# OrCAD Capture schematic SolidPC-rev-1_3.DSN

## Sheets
1 uSOM: size D; title: SolidPC; rev: 1.3
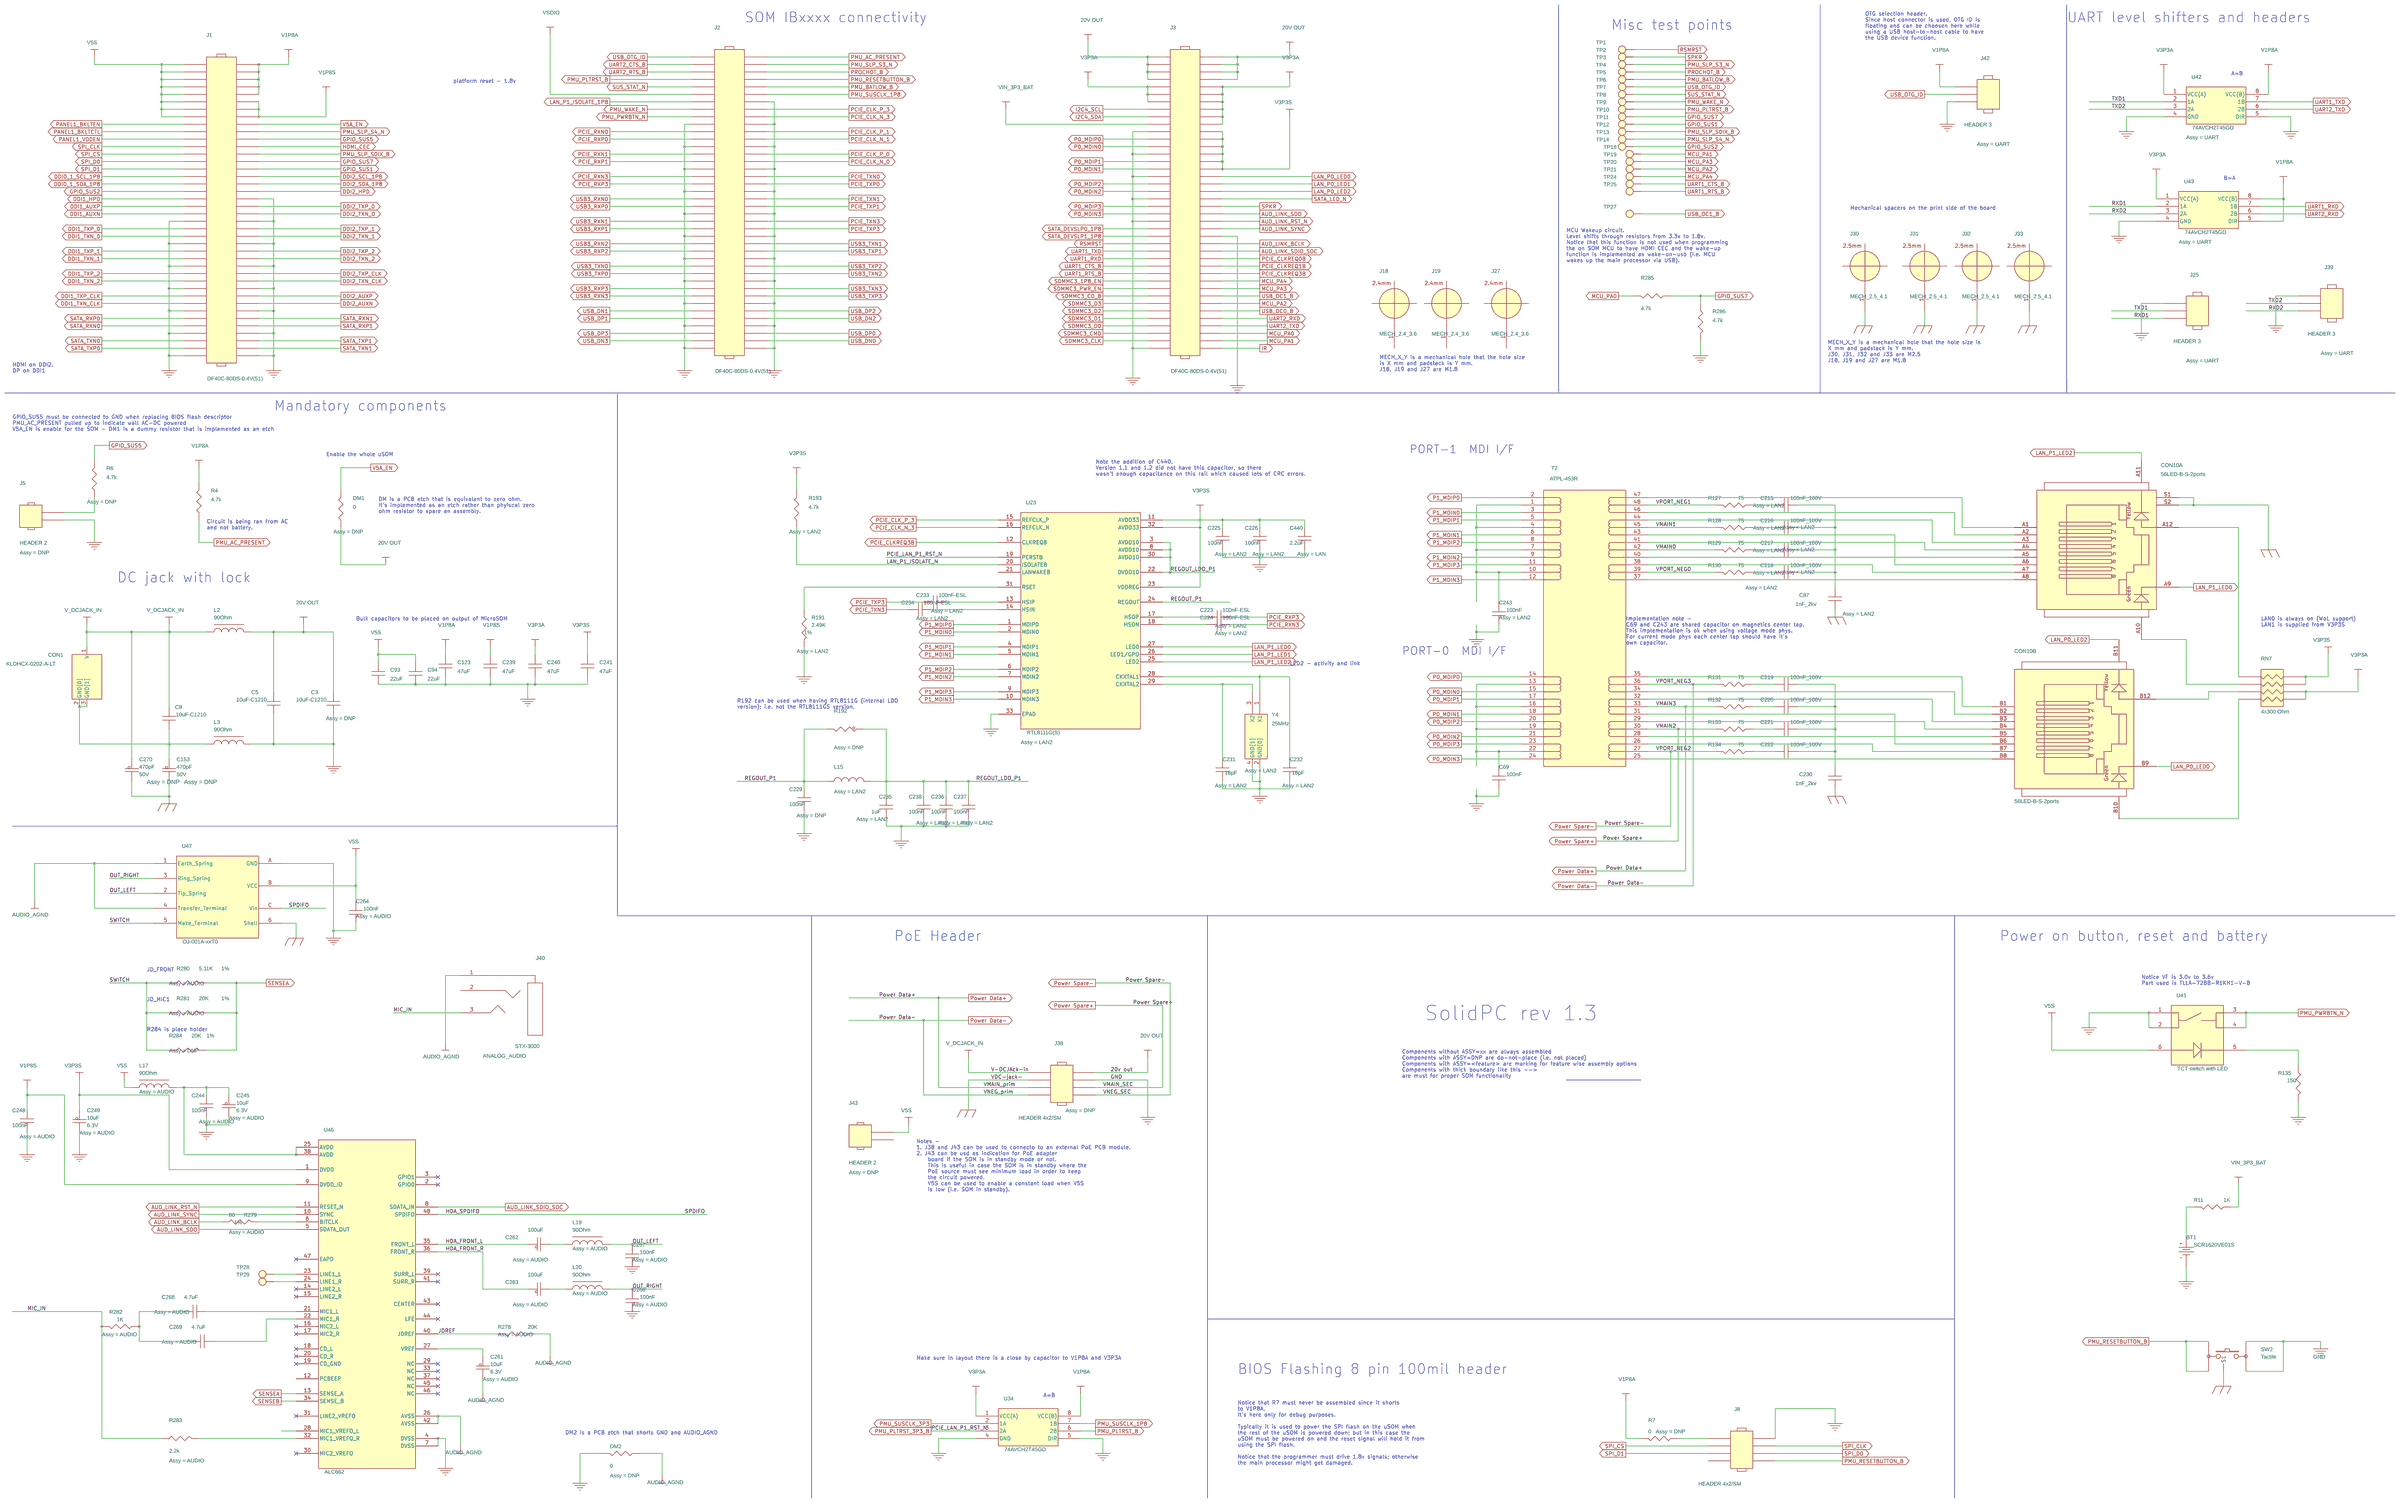
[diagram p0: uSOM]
2 External connectors: size D; rev: 1.1
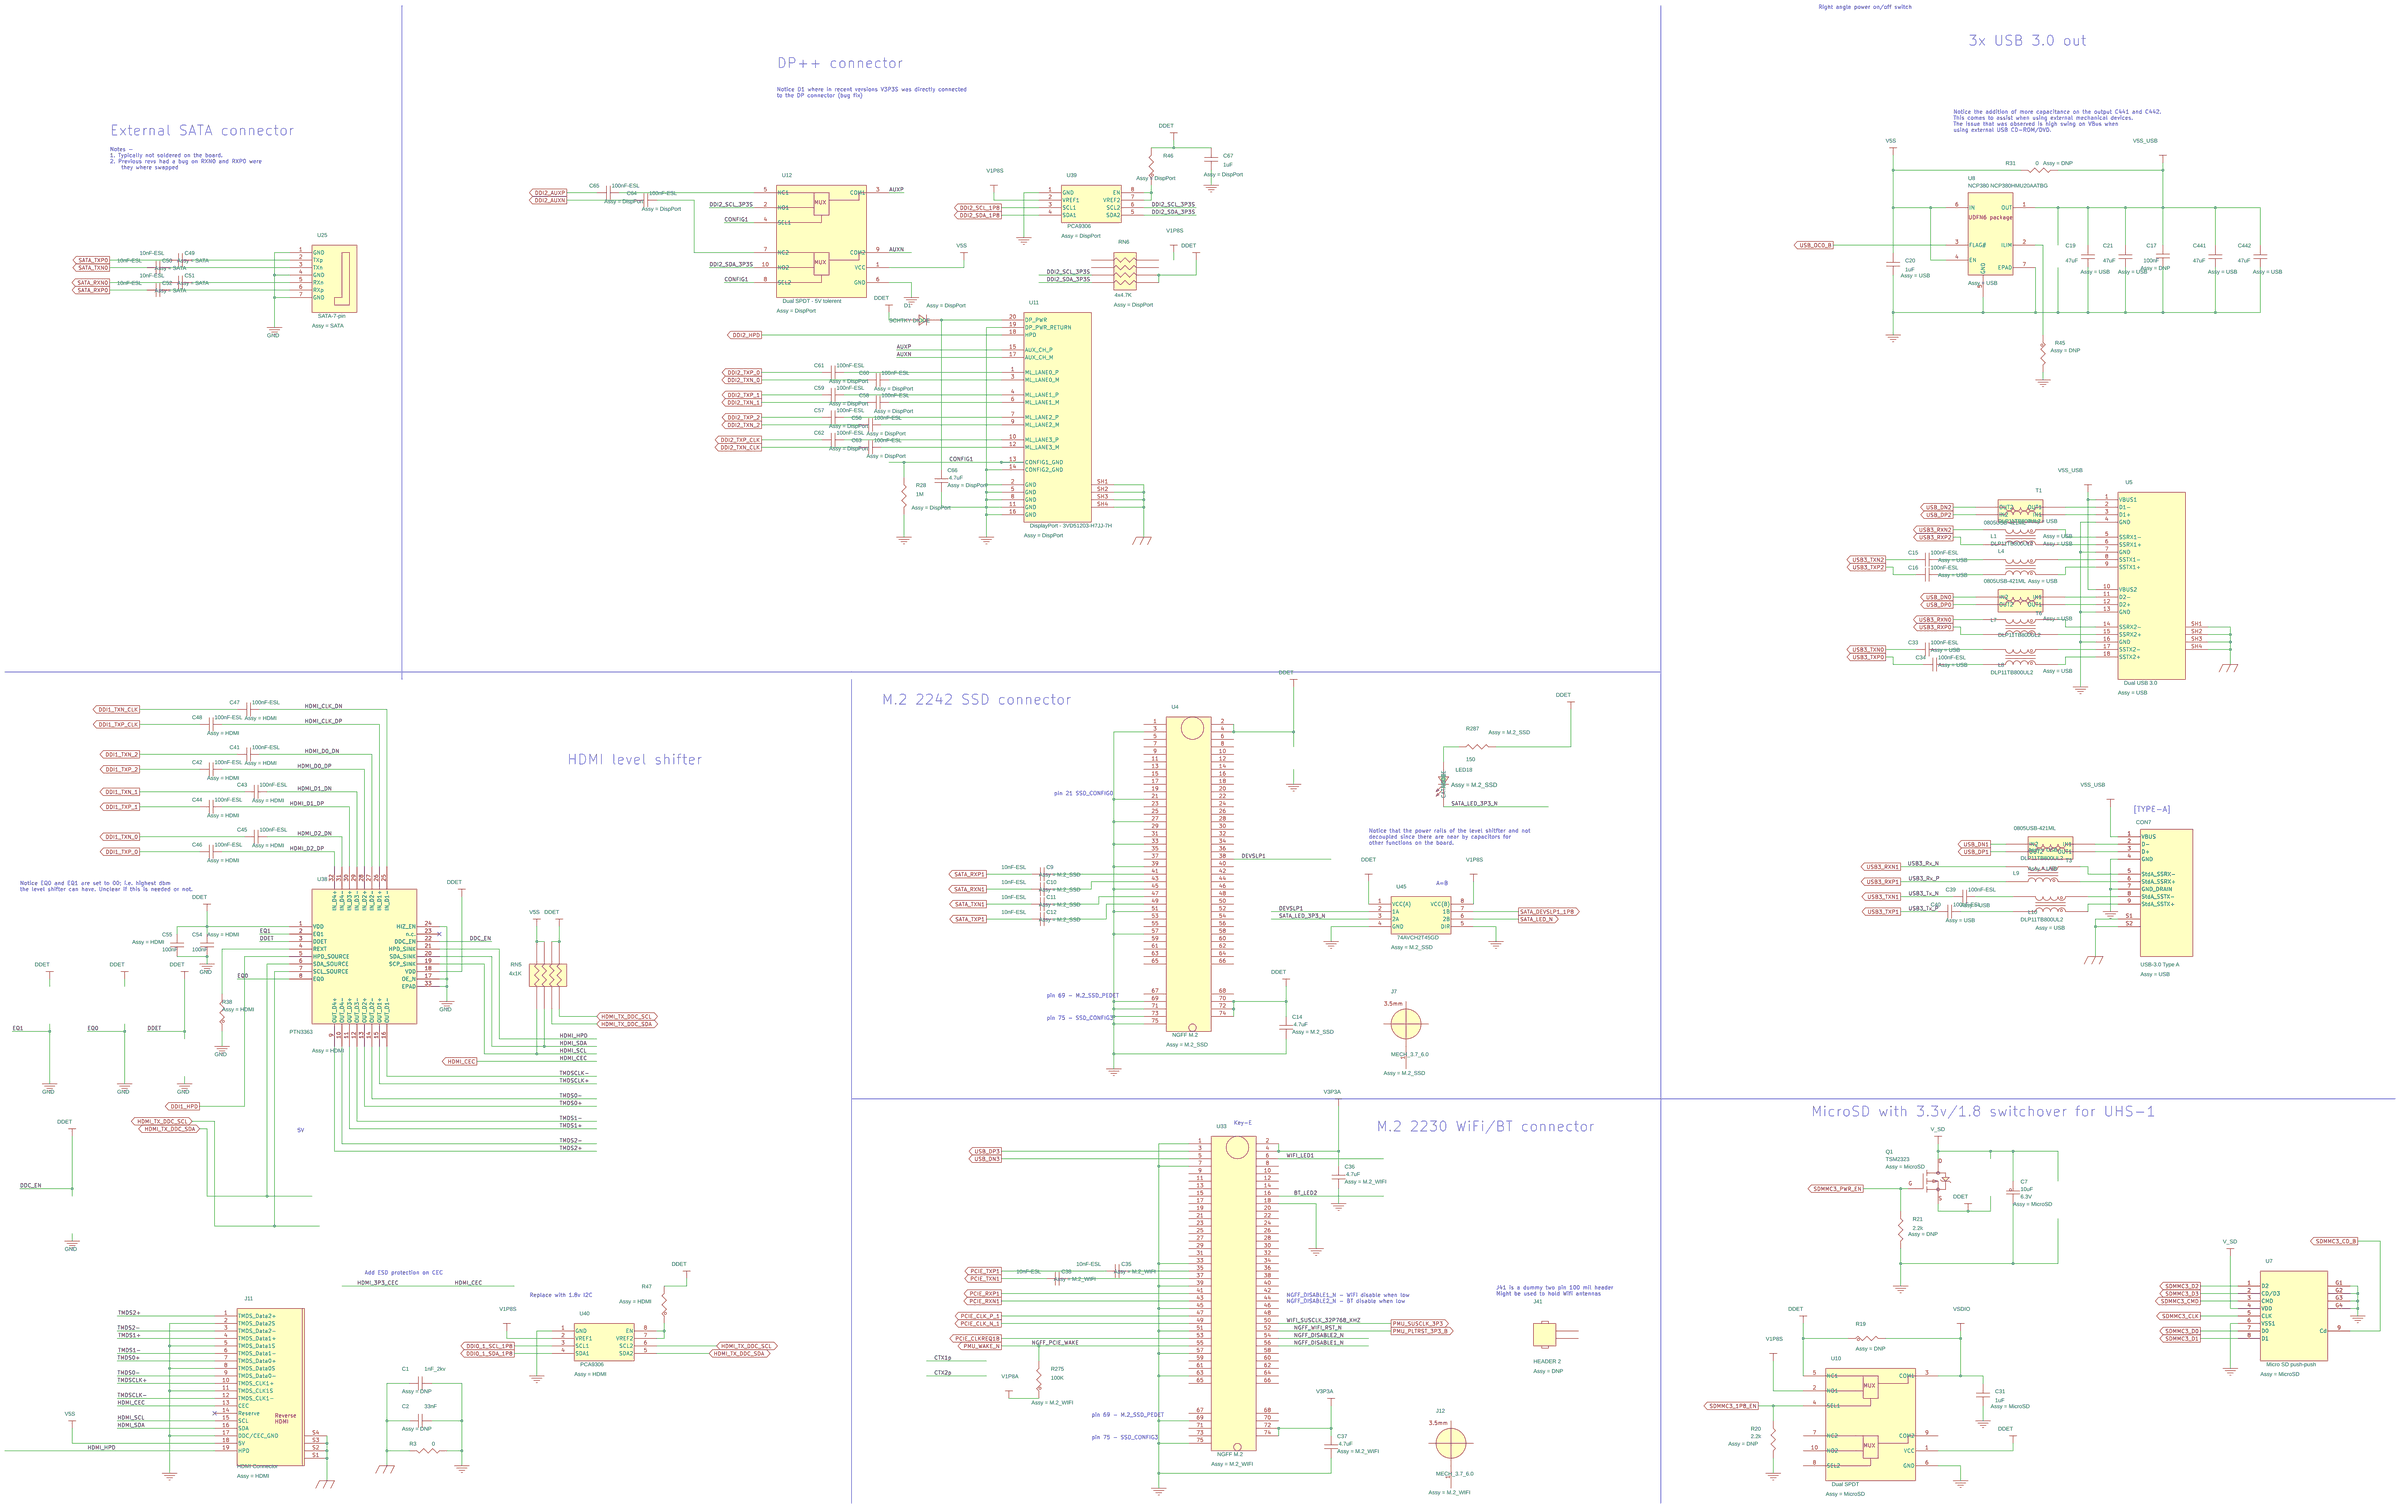
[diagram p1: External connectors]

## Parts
sheet External connectors
C1  1nF_2kv  [C1210]
C2  33nF  [C0402]
C7  10uF  [0603]
C9  10nF-ESL  [C0402]
C10  10nF-ESL  [C0402]
C11  10nF-ESL  [C0402]
C12  10nF-ESL  [C0402]
C14  4.7uF  [C0603]
C15  100nF-ESL  [C0402]
C16  100nF-ESL  [C0402]
C17  100nF  [C0402]
C19  47uF  [C1206]
C20  1uF  [C0402]
C21  47uF  [C1206]
C31  1uF  [0402]
C33  100nF-ESL  [C0402]
C34  100nF-ESL  [C0402]
C35  10nF-ESL  [C0402]
C36  4.7uF  [C0603]
C37  4.7uF  [C0603]
C38  10nF-ESL  [C0402]
C39  100nF-ESL  [C0402]
C40  100nF-ESL  [C0402]
C41  100nF-ESL  [C0402]
C42  100nF-ESL  [C0402]
C43  100nF-ESL  [C0402]
C44  100nF-ESL  [C0402]
C45  100nF-ESL  [C0402]
C46  100nF-ESL  [C0402]
C47  100nF-ESL  [C0402]
C48  100nF-ESL  [C0402]
C49  10nF-ESL  [C0402]
C50  10nF-ESL  [C0402]
C51  10nF-ESL  [C0402]
C52  10nF-ESL  [C0402]
C54  100nF  [C0402]
C55  100nF  [C0402]
C56  100nF-ESL  [C0402]
C57  100nF-ESL  [C0402]
C58  100nF-ESL  [C0402]
C59  100nF-ESL  [C0402]
C60  100nF-ESL  [C0402]
C61  100nF-ESL  [C0402]
C62  100nF-ESL  [C0402]
C63  100nF-ESL  [C0402]
C64  100nF-ESL  [C0402]
C65  100nF-ESL  [C0402]
C66  4.7uF  [C0603]
C67  1uF  [0402]
C441  47uF  [C1206]
C442  47uF  [C1206]
CON7  USB-3.0 Type A  [U3F09D-F1N2]
D1  SCHTKY DIODE  [DO-214AC]
J7  MECH_3.7_6.0  [MECH_3.7_6.0]
J11  HDMI Connector  [ABA-HDM-051]
J12  MECH_3.7_6.0  [MECH_3.7_6.0]
J41  HEADER 2
L1  DLP11TB800UL2  [DLP11TB800UL2]
L4  DLP11TB800UL2  [DLP11TB800UL2]
L7  DLP11TB800UL2  [DLP11TB800UL2]
L8  DLP11TB800UL2  [DLP11TB800UL2]
L9  DLP11TB800UL2  [DLP11TB800UL2]
L10  DLP11TB800UL2  [DLP11TB800UL2]
LED18  LED  [N/A]
Q1  TSM2323  [SOT23]
R3  0  [R0402]
R19  0  [0402]
R20  2.2k  [0402]
R21  2.2k  [0402]
R28  1M  [R0402]
R31  0  [R0402]
R38  12.4K  [0402]
R45  0  [0402]
R46  200K  [0402]
R47  200K  [0402]
R275  100K  [R0402]
R287  150  [R0402]
RN5  4x1K  [4xR0402]
RN6  4x4.7K  [YC124]
T1  0805USB-421ML  [CHOKE_0805]
T3  0805USB-421ML  [CHOKE_0805]
T6  0805USB-421ML  [CHOKE_0805]
U4  NGFF M.2  [NGFF]
U5  Dual USB 3.0
U7  Micro SD push-push  [ZM90]
U8  NCP380 NCP380HMU20AATBG  [TSOP-5]
U10  Dual SPDT  [R-PUQFN-N10]
U11  DisplayPort - 3VD51203-H7JJ-7H
U12  Dual SPDT - 5V tolerent  [R-PUQFN-N10]
U25  SATA-7-pin  [SATA-7-PIN]
U33  NGFF M.2  [NGFF]
U38  PTN3363  [HVQFN32]
U39  PCA9306  [US8]
U40  PCA9306  [US8]
U45  74AVCH2T45GD  [XSON8-SOT1116]
sheet uSOM
BT1  SCR1620VE01S  [N/A]
C3  10uF-C1210  [C1210]
C5  10uF-C1210  [C1210]
C8  10uF-C1210  [C1210]
C69  100nF  [C0402]
C87  1nF_2kv  [C1210]
C93  22uF  [C0603]
C94  22uF  [C0603]
C123  47uF  [C0805]
C153  470pF  [0402]
C215  100nF_100V  [C0603]
C216  100nF_100V  [C0603]
C217  100nF_100V  [C0603]
C218  100nF_100V  [C0603]
C219  100nF_100V  [C0603]
C220  100nF_100V  [C0603]
C221  100nF_100V  [C0603]
C222  100nF_100V  [C0603]
C223  100nF-ESL  [C0402]
C224  100nF-ESL  [C0402]
C225  100nF  [C0402]
C226  100nF  [C0402]
C229  100nF  [C0402]
C230  1nF_2kv  [C1210]
C231  18pF  [C0402]
C232  18pF  [C0402]
C233  100nF-ESL  [C0402]
C234  100nF-ESL  [C0402]
C235  1uF  [C0402]
C236  100nF  [C0402]
C237  100nF  [C0402]
C238  100nF  [C0402]
C239  47uF  [C0805]
C240  47uF  [C0805]
C241  47uF  [C0805]
C243  100nF  [C0402]
C244  100nF  [C0402]
C245  10uF  [0603]
C248  100nF  [C0402]
C249  10uF  [0603]
C261  10uF  [0603]
C262  100uF  [1210]
C263  100uF  [1210]
C264  100nF  [C0402]
C266  100nF  [C0402]
C267  100nF  [C0402]
C268  4.7uF  [C0603]
C269  4.7uF  [C0603]
C270  470pF  [0402]
C440  2.2uF  [C0402]
CON1  KLDHCX-0202-A-LT
CON10  56LED-B-S-2ports  [56LED-B-S-6ports]  (sections A,B)
DM1  0  [R0402]
DM2  0  [R0402]
J1  DF40C-80DS-0.4V(51)  [DF40HC-80DS]
J2  DF40C-80DS-0.4V(51)  [DF40HC-80DS]
J3  DF40C-80DS-0.4V(51)  [DF40HC-80DS]
J5  HEADER 2
J8  HEADER 4x2/SM  [M20]
J18  MECH_2.4_3.6  [MECH_2.4_3.6]
J19  MECH_2.4_3.6  [MECH_2.4_3.6]
J25  HEADER 3  [Header_3x1]
J27  MECH_2.4_3.6  [MECH_2.4_3.6]
J30  MECH_2.5_4.1  [MECH_2.5_4.1]
J31  MECH_2.5_4.1  [MECH_2.5_4.1]
J32  MECH_2.5_4.1  [MECH_2.5_4.1]
J33  MECH_2.5_4.1  [MECH_2.5_4.1]
J38  HEADER 4x2/SM  [M20]
J39  HEADER 3  [Header_3x1]
J40  STX-3000  [STX-3000]
J42  HEADER 3  [Header_3x1]
J43  HEADER 2
L2  90Ohm  [0805]
L3  90Ohm  [0805]
L15  4.7uH  [0806]
L17  90Ohm  [0805]
L19  90Ohm  [0805]
L20  90Ohm  [0805]
R4  4.7k  [R0402]
R6  4.7k  [R0402]
R7  0  [R0402]
R11  1K  [R0402]
R127  75  [R0402]
R128  75  [R0402]
R129  75  [R0402]
R130  75  [R0402]
R131  75  [R0402]
R132  75  [R0402]
R133  75  [R0402]
R134  75  [R0402]
R135  150  [R0402]
R191  2.49K  [R0402]
R192  0  [0402]
R193  4.7k  [R0402]
R278  20K  [R0402]
R279  80  [R0402]
R280  5.11K  [R0402]
R281  20K  [R0402]
R282  1K  [R0402]
R283  2.2k  [0402]
R284  20K  [R0402]
R285  4.7k  [R0402]
R286  4.7k  [R0402]
RN7  4x300 Ohm  [YC124]
SW2  Tactile  [N/A]
T2  ATPL-453R  [ATPL-453R]
TP1  TP_TH08  [HOLE_0p8]
TP2  TP_TH08  [HOLE_0p8]
TP3  TP_TH08  [HOLE_0p8]
TP4  TP_TH08  [HOLE_0p8]
TP5  TP_TH08  [HOLE_0p8]
TP6  TP_TH08  [HOLE_0p8]
TP7  TP_TH08  [HOLE_0p8]
TP8  TP_TH08  [HOLE_0p8]
TP9  TP_TH08  [HOLE_0p8]
TP10  TP_TH08  [HOLE_0p8]
TP11  TP_TH08  [HOLE_0p8]
TP12  TP_TH08  [HOLE_0p8]
TP13  TP_TH08  [HOLE_0p8]
TP14  TP_TH08  [HOLE_0p8]
TP18  TP_TH08  [HOLE_0p8]
TP19  TP_TH08  [HOLE_0p8]
TP20  TP_TH08  [HOLE_0p8]
TP21  TP_TH08  [HOLE_0p8]
TP24  TP_TH08  [HOLE_0p8]
TP25  TP_TH08  [HOLE_0p8]
TP27  TP_TH08  [HOLE_0p8]
TP28  TP_TH08  [HOLE_0p8]
TP29  TP_TH08  [HOLE_0p8]
U23  RTL8111G(S)  [QFN32]
U34  74AVCH2T45GD  [XSON8-SOT1116]
U41  TCT switch with LED
U42  74AVCH2T45GD  [XSON8-SOT1116]
U43  74AVCH2T45GD  [XSON8-SOT1116]
U46  ALC662  [LQFP-48]
U47  OJ-001A-xxT0
Y4  25MHz  [S3225]

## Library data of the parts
C1 = Cap: CHIP CAP 1nF 2KV 1610; Assy: DNP; MFG_NAME01: Hitano; MFG_PN01: 1210N102J202NT; Manufacturer: Hitano; Manufacturer Name: Hitano; Manufacturer P/N: 1210N102J202NT; PRIORITY_PN: CA60001; SolidRun P/N: CA60001; Updated: 2015-09-14 13:40:19; Datasheet: <null>
C2 = Cap: CHIP CAP 33nF 6.3V 0402 X5R; Assy: DNP; MFG_NAME01: SAMSUNG; MFG_PN01: CL05B333KP5NNNC; Manufacturer: Murata; Manufacturer Name: Murata; Manufacturer P/N: GRM155R71A333KA01D; SolidRun P/N: CA20011; Updated: 2015-09-14 13:40:19; Datasheet: <null>
C7 = CAP_NP: CAP CER 10UF 6.3V 10% X5R 0603; AGILE_PN: 150-77832; Assy: MicroSD; CAD_APPROVED: Yes; FPLIST: CC0603_OV,CC0603,0603_CC; HEIGHT: 1.0MM; MFG_NAME01: TDK; MFG_PN01: C1608X5R0J106KT; ROHS: Yes; SIGNAL_MODEL: DEFAULT_CAPACITOR_1e+07pF_2_1; SolidRun P/N: CA30001; Tolerance: 10%; VOLTAGE: 6.3V; WVDC: 6.3V
C9-C12 = Cap: CHIP CAP 10nF 25V 0402 X7R; Assy: M.2_SSD; Manufacturer: Capax; Manufacturer P/N: 0402X103K250SNT; Part Number: 0402X103K250SNT; Power: 0; SolidRun P/N: CA20002; Tolerance: 10%; Datasheet: <null>
C14 = Cap: CAP CER 0603 4.7UF 10V 10% X5R; Assy: M.2_SSD; Manufacturer: Hitano; Manufacturer P/N: 0603B475K160NU; Part Number: C4750805-X5R-25V; SolidRun P/N: CA30003; Updated: 2015-02-17 20:35:06; Datasheet: <null>
C15 C16 C33 C34 C39 C40 = Cap: CAP CER 100NF 16V 10% X7R 0402; Assy: USB; FPLIST: 0402_SQR21,0402_RND,0402; Manufacturer: CAPAX; Manufacturer P/N: 0402X104K250SNT; Part Number: 0402X104K250SNT; SolidRun P/N: CA20090; Updated: 2015-02-17 20:35:06; Datasheet: <null>
C17 = Cap: CAP CER 0402 100nF 10V 10% X7R; Assy: DNP; FPLIST: 0402_SQR21,0402_RND,0402; Manufacturer: samsung; Manufacturer P/N: CL05B104KP5NNNC; Part Number: C1040402-X7R-16V; SolidRun P/N: CA20001; Updated: 2015-02-17 20:35:06; Datasheet: <null>
C19 C21 C441 C442 = Cap: CAP CER 1206 47UF 6.3V 20% X5R; Assy: USB; Manufacturer: murata; Manufacturer P/N: GRM31CR60J476ME19L; Part Number: GMC31X5R476M10NTLF; SolidRun P/N: CA50001; Updated: 2015-02-17 20:35:06; Datasheet: <null>
C20 = Cap: CAP CER 0402 1uF 10V 10% X5R; Assy: USB; Manufacturer: samsung; Manufacturer P/N: CL05A105KP5NNNC; Part Number: C1050603-X7R-16V; SolidRun P/N: CA20005; Updated: 2015-02-17 20:35:06; Datasheet: <null>
C31 = Cap: CHIP CAP 33nF 6.3V 0402 X5R; Assy: MicroSD; MFG_NAME01: SAMSUNG; MFG_PN01: CL05B333KP5NNNC; SolidRun P/N: CA20005; Tolerance: 20%
C35 C38 = Cap: CHIP CAP 10nF 25V 0402 X7R; Assy: M.2_WIFI; Manufacturer: Capax; Manufacturer P/N: 0402X103K250SNT; Part Number: 0402X103K250SNT; Power: 0; SolidRun P/N: CA20002; Tolerance: 10%; Datasheet: <null>
C36 C37 = Cap: CAP CER 0603 4.7UF 10V 10% X5R; Assy: M.2_WIFI; Manufacturer: Hitano; Manufacturer P/N: 0603B475K160NU; Part Number: C4750805-X5R-25V; SolidRun P/N: CA30003; Updated: 2015-02-17 20:35:06; Datasheet: <null>
C41-C48 = Cap: CAP CER 100NF 16V 10% X7R 0402; Assy: HDMI; FPLIST: 0402_SQR21,0402_RND,0402; Manufacturer: CAPAX; Manufacturer P/N: 0402X104K250SNT; Part Number: 0402X104K250SNT; SolidRun P/N: CA20090; Updated: 2015-02-17 20:35:06; Datasheet: <null>
C49-C52 = Cap: CHIP CAP 10nF 25V 0402 X7R; Assy: SATA; Manufacturer: Capax; Manufacturer P/N: 0402X103K250SNT; Part Number: 0402X103K250SNT; Power: 0; SolidRun P/N: CA20002; Tolerance: 10%; Datasheet: <null>
C54 C55 = Cap: CAP CER 0402 100nF 10V 10% X7R; Assy: HDMI; Manufacturer: samsung; Manufacturer P/N: CL05B104KP5NNNC; Part Number: C1040402-X7R-16V; Power: <null>; SolidRun P/N: CA20001; Tolerance: 6.3V 20% X7R; Datasheet: <null>
C56-C65 = Cap: CAP CER 100NF 16V 10% X7R 0402; Assy: DispPort; FPLIST: 0402_SQR21,0402_RND,0402; Manufacturer: CAPAX; Manufacturer P/N: 0402X104K250SNT; Part Number: 0402X104K250SNT; SolidRun P/N: CA20090; Updated: 2015-02-17 20:35:06; Datasheet: <null>
C66 = Cap: CAP CER 0603 4.7UF 10V 10% X5R; Assy: DispPort; Manufacturer: Hitano; Manufacturer P/N: 0603B475K160NU; Part Number: C4750805-X5R-25V; SolidRun P/N: CA30003; Updated: 2015-02-17 20:35:06; Datasheet: <null>
C67 = Cap: CHIP CAP 33nF 6.3V 0402 X5R; Assy: DispPort; MFG_NAME01: SAMSUNG; MFG_PN01: CL05B333KP5NNNC; SolidRun P/N: CA20005; Tolerance: 20%
CON7 = USB3_2: USB-3.0 Host connector; Assy: USB; Manufacturer: Genesis; Manufacturer P/N: USAR-2F09-AB63T1H; Part Number: USAR-2F09-AB63T1H; SolidRun P/N: CO00526; Updated: 2015-02-17 20:35:06; Datasheet: <null>
D1 = DIODE: Diode Schottky 30V 2A Surface Mount SMA; Assy: DispPort; Manufacturer: Diodes; Manufacturer P/N: B230A-13-F; SolidRun P/N: DI00225; Tolerance: 30V/2A; Datasheet: https://www.diodes.com/assets/Datasheets/ds13004.pdf
J7 = MECH_4.5_4: Assy: M.2_SSD; PRIORITY_PN: MCH0008; SolidRun P/N: MCH0008
J11 = HDMI_connector_0: Assy: HDMI; MFG_NAME01: LOTES; MFG_PN01: ABA-HDM-051-P01; SolidRun P/N: CO00559; Datasheet: http://www.lotes.cc/upload/Customer_drawing/HDMI/ABA-HDM-051_(REV.C).pdf
J12 = MECH_4.5_4: Assy: M.2_WIFI; PRIORITY_PN: MCH0008; SolidRun P/N: MCH0008
J5 J41 J43 = HEADER_2: Assy: DNP; Manufacturer: FCI; Note: 100 mil two pins; Power: 0; Price: 0.054; SolidRun P/N: CO00049; Source: Mouser; Source P/N: 649-68000-101HLF; Datasheet: http://portal.fciconnect.com/Comergent/adirect/fci?cmd=catCustomerDrawing&productName=68000-101HLF
L1 L4 L7-L10 = CHOKE_CMx2: Common Mode Filters / Chokes 0504 80ohm EMI Suppression Fltr; Assy: USB; Manufacturer: Murata; Manufacturer P/N: DLP11TB800UL2L; SolidRun P/N: IN00033; Updated: 2015-02-17 20:35:06; Datasheet: http://www.mouser.com/ds/2/281/Murata%20DL_PL%20Series-202927.pdf
LED18 = LED: Indication LED 0603 - Green; Assy: M.2_SSD; Manufacturer: Everlight; PRIORITY_PN: DI00210; SolidRun P/N: DI00210; Updated: 2015-02-17 20:35:06; Datasheet: http://download.siliconexpert.com/pdfs/2007/08/07/semi_b/manual/ele/lamps/ds300089.pdf
Q1 = IRF4905_TO_2: 20V P-Channel MOSFET; Assy: MicroSD; SolidRun P/N: IC00666
R3 = Resistor_tolerance_0: RES 0402 1/16W 0? 5%; FPLIST: RC0402_25,RC0402_HD,RC0402_X2,0402_CC; MFG_NAME01: YAGEO; MFG_PN01: RC0402JR-070RL; Manufacturer: Yageo; Manufacturer Name: Yageo; Manufacturer P/N: RC0402JR-070RL; Manufacturer's Part Number: RC0402JR-070RL; SolidRun P/N: RE20009; Updated: 2015-09-14 13:40:19; Datasheet: <null>
R19 R192 = RES: RES MF ZERO OHM 1/10W -- 0402; AGILE_PN: 470-79965; Assy: DNP; CAD_APPROVED: Yes; FPLIST: RC0402_25,RC0402_HD,RC0402_X2,0402_CC; ROHS: Yes; SIGNAL_MODEL: DEFAULT_RESISTOR_0.001OHM_2_1; SolidRun P/N: RE20009
R20 R21 = Resistor: CHIP RES 2.2K 1/16W 0402; Assy: DNP; MFG_NAME01: YAGEO; MFG_PN01: RC0402JR-072K2L; SolidRun P/N: RE20204; Tolerance: 5%
R28 = Resistor_tolerance_0: RES 0402 1/16W 1M 5%; Assy: DispPort; FPLIST: RC0402_25,RC0402_HD,RC0402_X2,0402_CC; MFG_NAME01: YAGEO; MFG_PN01: RC0402JR-070RL; Manufacturer: Yageo; Manufacturer P/N: RC0402FR-071ML; SolidRun P/N: RE20416; Updated: 2015-02-17 20:35:06
R7 R31 = Resistor: RES 0402 1/16W 0? 5%; Assy: DNP; Manufacturer: Yageo; Manufacturer P/N: RC0402JR-070RL; Part Number: R0000805; Power: <null>; SolidRun P/N: RE20009; Tolerance: NA; Datasheet: <null>
R38 = RES: RES MF 12.4 KOhm 0402 1%; AGILE_PN: 470-79965; Assy: HDMI; CAD_APPROVED: Yes; FPLIST: RC0402_25,RC0402_HD,RC0402_X2,0402_CC; ROHS: Yes; SIGNAL_MODEL: DEFAULT_RESISTOR_0.001OHM_2_1; SolidRun P/N: RE20457
R45 = RES: RES MF ZERO OHM 1/10W -- 0402; Assy: DNP; CAD_APPROVED: Yes; FPLIST: RC0402_25,RC0402_HD,RC0402_X2,0402_CC; ROHS: Yes; SIGNAL_MODEL: DEFAULT_RESISTOR_0.001OHM_2_1; SolidRun P/N: RE20009
R46 = RES: RES MF 200 KOHM 1/10W -- 0402; AGILE_PN: 470-79965; Assy: DispPort; CAD_APPROVED: Yes; FPLIST: RC0402_25,RC0402_HD,RC0402_X2,0402_CC; ROHS: Yes; SIGNAL_MODEL: DEFAULT_RESISTOR_0.001OHM_2_1; SolidRun P/N: RE20036
R47 = RES: RES MF 200 KOHM 1/10W -- 0402; AGILE_PN: 470-79965; Assy: HDMI; CAD_APPROVED: Yes; FPLIST: RC0402_25,RC0402_HD,RC0402_X2,0402_CC; ROHS: Yes; SIGNAL_MODEL: DEFAULT_RESISTOR_0.001OHM_2_1; SolidRun P/N: RE20036
R275 = RES: RES 0402 1/16W 100K 1%; Assy: M.2_WIFI; FPLIST: RC0402_25,RC0402_HD,0402_CC; ROHS: Yes; SIGNAL_MODEL: DEFAULT_RESISTOR_10000OHM_2_1; SolidRun P/N: RE20015; Tolerance: 1%; Updated: 2015-02-17 20:35:06; Datasheet: <null>
R287 = Resistor: RES 0402 1/16W 150 Ohm 1%; Assy: M.2_SSD; Manufacturer: Yageo; Manufacturer P/N: RC0402FR-0710KL; Part Number: R1030402-1%; Power: <null>; SolidRun P/N: RE20014; Tolerance: 5%; Datasheet: <null>
RN5 = RESISTOR_DIP_4: 4 Elements 1 KOhm 5%; Power: <null>; SolidRun P/N: RN00041; Tolerance: 1%; Datasheet: http://www.ctscorp.com/components/Datasheets/CTSChipArrayDs.pdf
RN6 = RESISTOR_DIP_4: 4.7K Resistor Network 4x0402 5%; Assy: DispPort; MFG_NAME01: YAGEO; MFG_PN01: YC124-JR-074K7L; Power: 0; SolidRun P/N: RN00002; Tolerance: 1%; Wattage: 1/10W; Datasheet: http://www.yageo.ru/pdf/YC124.pdf
T1 T3 T6 = DLW21HN121SQ2: Common Mode Filter USB 2.0; Assy: USB; Manufacturer: Coilcraft; Manufacturer P/N: 0805USB-421MLC; Part Number: 0805USB-421MLC; SolidRun P/N: IN00016; Updated: 2015-02-17 20:35:06; Datasheet: http://www.mouser.com/ds/2/597/0805usb-463502.pdf
U4 = NGFF_M.2: Assy: M.2_SSD; SolidRun P/N: CO00514
U5 = Dual_USB_3_0.0: Assy: USB; SolidRun P/N: CO00554
U7 = CJ-WK21923-R6SS6_0: SD/MMC card connector; Assy: MicroSD; MFG_NAME01: CEN LINK; MFG_PN01: ZM90-15000-0BR1; SolidRun P/N: CO00091; Datasheet: ZM90-15000-0BR1-(C).pdf
U8 = NCP380_2: Adjustable USB Current limiter; Assy: USB; Manufacturer: OnSemi; Manufacturer P/N: NCP380HMU20AATBG; SolidRun P/N: IC01034; Datasheet: http://www.onsemi.com/pub_link/Collateral/NCP380-D.PDF
U10 = Dual_SPDT: Dual analog switch; Assy: MicroSD; MFG_NAME01: TI; MFG_PN01: TS3A5223RSWR; SolidRun P/N: IC00220; Datasheet: http://www.mouser.com/ds/2/405/scds339a-261259.pdf
U11 = DisplayPort_-_3VD51203-H7JJ-7H: Display Port full size; Assy: DispPort; SolidRun P/N: CO00555
U12 = Dual_SPDT: Dual analog switch; Assy: DispPort; SolidRun P/N: IC01039
U25 = SATA-7-pin: Assy: SATA; SolidRun P/N: CO00513
U33 = NGFF_M.2: Assy: M.2_WIFI; SolidRun P/N: CO00552
U38 = PTN3363: DP to HDMI level shifter; Assy: HDMI; SolidRun P/N: IC01036
U39 = PCA9306: Assy: DispPort; SolidRun P/N: IC01040
U40 = PCA9306: Assy: HDMI; SolidRun P/N: IC01040
U45 = 74AVCH2T45GN: Dual-bit, dual-supply voltage level translator/transceiver; 3-state; Assy: M.2_SSD; SolidRun P/N: IC01021
BT1 = Battery_1: RTC Battery xV/yA; Manufacturer: JL Worldwide; Manufacturer P/N: <null>; Power: 0; Price: 0.26; SolidRun P/N: BT00001; Source: Mouser; Tolerance: <null>; Updated: 2015-09-14 13:40:19
C3 = Cap: CHIP CAP 10uF 50V 10% X7R 1210; Assy: DNP; Manufacturer: SAMSUNG; Manufacturer P/N: CL32B106KBJNNWE; SolidRun P/N: CA60004; Updated: 2015-07-16 09:53:12
C5 C8 = Cap: CHIP CAP 10uF 50V 10% X7R 1210; Manufacturer: SAMSUNG; Manufacturer P/N: CL32B106KBJNNWE; SolidRun P/N: CA60004; Updated: 2015-07-16 09:53:12
C69 = Cap: CAP CER 0402 100nF 10V 10% X7R; FPLIST: 0402_SQR21,0402_RND,0402; Manufacturer: samsung; Manufacturer P/N: CL05B104KP5NNNC; Part Number: C1040402-X7R-16V; SolidRun P/N: CA20001; Updated: 2015-02-17 20:35:06; Datasheet: <null>
C87 = Cap: CHIP CAP 1nF 2KV 1610; Assy: LAN2; MFG_NAME01: Hitano; MFG_PN01: 1210N102J202NT; Manufacturer: Hitano; Manufacturer P/N: 1210N102J202NT; PRIORITY_PN: CA60001; SolidRun P/N: CA60001; Updated: 2015-02-17 20:35:06; Datasheet: <null>
C93 C94 = Cap: CAP CER 0603 22UF 6.3V 20% X5R; Manufacturer: Samsung; Manufacturer P/N: CL10A226MQ8NRNE; Part Number: C2260805-X5R-6.3V; Power: <null>; SolidRun P/N: CA30002; Tolerance: 6.3V 20% X5R; Datasheet: <null>
C123 C239-C241 = Cap: CAP CER 0805 47UF 4V 20% X5R; Power: <null>; SolidRun P/N: CA40006; Tolerance: 4V 20% X5R; Datasheet: <null>
C153 C270 = CAP_NP: CAP CER 470PF 50V 10% X7R 0402; AGILE_PN: 150-75452; Assy: DNP; CAD_APPROVED: Yes; FPLIST: CC0402_25,CC0402_HD,0402_CC; HEIGHT: 0.55MM; MFG_NAME01: MURATA; MFG_PN01: GRM155R71H471KA01D; ROHS: Yes; ROOM: RGMII_PHY; SIGNAL_MODEL: DEFAULT_CAPACITOR_470pF_2_1; SolidRun P/N: CA20082; Tolerance: 10%; VOLTAGE: 50V; WVDC: 50V
C215-C218 = Cap: CAP CER 0.1 uF 100 V 10% X7R 0603; Assy: LAN2; FPLIST: 0402_SQR21,0402_RND,0402; Manufacturer: samsung; Manufacturer P/N: CL10B104KC8NNNC; Part Number: C1040402-X7R-16V; SolidRun P/N: CA30006; Updated: 2015-02-17 20:35:06; Datasheet: <null>
C219-C222 = Cap: CAP CER 0.1 uF 100 V 10% X7R 0603; FPLIST: 0402_SQR21,0402_RND,0402; Manufacturer: samsung; Manufacturer P/N: CL10B104KC8NNNC; Part Number: C1040402-X7R-16V; SolidRun P/N: CA30006; Updated: 2015-02-17 20:35:06; Datasheet: <null>
C223 C224 C233 C234 = Cap: CAP CER 100NF 16V 10% X7R 0402; Assy: LAN2; FPLIST: 0402_SQR21,0402_RND,0402; Manufacturer: CAPAX; Manufacturer P/N: 0402X104K250SNT; Part Number: 0402X104K250SNT; SolidRun P/N: CA20090; Updated: 2015-02-17 20:35:06; Datasheet: <null>
C225 C226 C236-C238 = Cap: CAP CER 0402 100nF 10V 10% X7R; Assy: LAN2; Manufacturer: samsung; Manufacturer P/N: CL05B104KP5NNNC; Part Number: C1040402-X7R-16V; Power: <null>; SolidRun P/N: CA20001; Tolerance: 6.3V 20% X7R; Datasheet: <null>
C229 = Cap: CAP CER 0402 100nF 10V 10% X7R; Assy: DNP; Manufacturer: samsung; Manufacturer P/N: CL05B104KP5NNNC; Part Number: C1040402-X7R-16V; Power: <null>; SolidRun P/N: CA20001; Tolerance: 6.3V 20% X7R; Datasheet: <null>
C230 = Cap: CHIP CAP 1nF 2KV 1610; MFG_NAME01: Hitano; MFG_PN01: 1210N102J202NT; Manufacturer: Hitano; Manufacturer P/N: 1210N102J202NT; PRIORITY_PN: CA60001; SolidRun P/N: CA60001; Updated: 2015-02-17 20:35:06; Datasheet: <null>
C231 C232 = Cap: CAP CER 0402 18pF 50V 5% C0G; Assy: LAN2; Manufacturer: Murata; Manufacturer P/N: GRM1555C1H220JA01D; Part Number: C2200402-NPO-50V; Power: <null>; SolidRun P/N: CA20017; Tolerance: 4V 5% C0G; Datasheet: <null>
C235 = Cap: CAP CER 0402 1uF 10V 10% X5R; Assy: LAN2; Manufacturer: samsung; Manufacturer P/N: CL05A105KP5NNNC; Part Number: C1050603-X7R-16V; Power: <null>; SolidRun P/N: CA20005; Tolerance: 6.3V 20% X5R; Datasheet: <null>
C243 = Cap: CAP CER 0402 100nF 10V 10% X7R; Assy: LAN2; FPLIST: 0402_SQR21,0402_RND,0402; Manufacturer: samsung; Manufacturer P/N: CL05B104KP5NNNC; Part Number: C1040402-X7R-16V; SolidRun P/N: CA20001; Updated: 2015-02-17 20:35:06; Datasheet: <null>
C244 C248 = Cap: CAP CER 0402 100nF 10V 10% X7R; Assy: AUDIO; Manufacturer: samsung; Manufacturer P/N: CL05B104KP5NNNC; Part Number: C1040402-X7R-16V; Power: <null>; SolidRun P/N: CA20001; Tolerance: 6.3V 20% X7R; Datasheet: <null>
C245 C249 C261 = CAP_NP: CAP CER 10UF 6.3V 10% X5R 0603; AGILE_PN: 150-77832; Assy: AUDIO; CAD_APPROVED: Yes; FPLIST: CC0603_OV,CC0603,0603_CC; HEIGHT: 1.0MM; MFG_NAME01: TDK; MFG_PN01: C1608X5R0J106KT; ROHS: Yes; SIGNAL_MODEL: DEFAULT_CAPACITOR_1e+07pF_2_1; SolidRun P/N: CA30001; Tolerance: 10%; VOLTAGE: 6.3V; WVDC: 6.3V
C262 C263 = CAP_NP: CAP CER 100UF 6.3V 20% X5R 1210; AGILE_PN: 150-77832; Assy: AUDIO; CAD_APPROVED: Yes; FPLIST: CC0603_OV,CC0603,0603_CC; HEIGHT: 1.0MM; ROHS: Yes; SIGNAL_MODEL: DEFAULT_CAPACITOR_1e+07pF_2_1; SolidRun P/N: CA60002; Tolerance: 20%
C264 C266 C267 = Cap: CAP CER 0402 100nF 10V 10% X7R; Assy: AUDIO; FPLIST: 0402_SQR21,0402_RND,0402; Manufacturer: samsung; Manufacturer P/N: CL05B104KP5NNNC; Part Number: C1040402-X7R-16V; SolidRun P/N: CA20001; Updated: 2015-02-17 20:35:06; Datasheet: <null>
C268 C269 = Cap: CAP CER 0603 4.7UF 10V 10% X5R; Assy: AUDIO; Manufacturer: Hitano; Manufacturer P/N: 0603B475K160NU; Part Number: C4750805-X5R-25V; SolidRun P/N: CA30003; Updated: 2015-02-17 20:35:06; Datasheet: <null>
C440 = Cap: CAP CER 0402 2.2uF 6.3V 20% X5R; Assy: LAN; Manufacturer: Murata; Manufacturer P/N: GRM155R60J225ME87D; Part Number: C2251206-X7R-10V; Power: <null>; SolidRun P/N: CA20117; Tolerance: 4V 20% X5R; Datasheet: <null>
CON1 = POWER_JACK: Power Jack; Manufacturer: <null>; Manufacturer P/N: <null>; Part Number: KLDX-0202-B-LT; SolidRun P/N: CO00053; Updated: 2015-07-16 09:53:12
CON10 = 56LED-B-S-2ports_1: SolidRun P/N: CO00543
DM1 DM2 = Resistor: DUMMY LAYOUT SHORTED RES 0402 1/16W 0? 5%; Assy: DNP; Manufacturer: Yageo; Manufacturer P/N: RC0402JR-070RL; Part Number: R0000402; Power: <null>; SolidRun P/N: DM00003; Tolerance: NA; Datasheet: <null>
J1-J3 = HEADER_40x2_SM: Board-to-Board 80 pins, 0.4mm pitch; MFG_NAME01: Hirose; Manufacturer: Hirose; PRIORITY_PN: CO00017; SolidRun P/N: CO00017; Tolerance: <null>; Updated: 2015-07-16 09:53:12; Datasheet: <null>
J8 = HEADER_4x2_SM: Two row 100-mil through hole header; MFG_NAME01: HARWIN; MFG_PN01: M20-9980446; SolidRun P/N: CO00573; Datasheet: http://www.harwin.com/include/downloads/drawings/M20-976.PDF
J18 J19 J27 = MECH_2.5_4: SolidRun P/N: MCH0007
J25 J39 J42 = HEADER_3: 100 mil header 3 x 1; Assy: UART; Manufacturer: cvilux; Manufacturer P/N: CH31032V200-NH; SolidRun P/N: CO00509; Tolerance: <null>; Updated: 2015-07-16 09:53:12; Datasheet: <null>
J30-J33 = MECH_3.5_4: SolidRun P/N: MCH0009
J38 = HEADER_4x2_SM: Two row 100-mil through hole header; Assy: DNP; MFG_NAME01: HARWIN; MFG_PN01: M20-9980446; SolidRun P/N: CO00573; Datasheet: http://www.harwin.com/include/downloads/drawings/M20-976.PDF
J40 = STX-3000: ASSY_OPT: ANALOG_AUDIO; SolidRun P/N: CO00516
L2 L3 = Ferrite_Bead: Filter Bead 90ohms 25%; MFG_NAME01: VIKING; MFG_PN01: CB05YTYH900; Manufacturer: VIKING; Manufacturer P/N: CB05YTYH900; PRIORITY_PN: IN00001; SolidRun P/N: IN00001; Tolerance: 25%; Updated: 2015-07-16 09:53:12; Datasheet: <null>
L15 = INDUCTOR: IND PWR 4.7UH@1MH 1.1A 20% SMD; AGILE_PN: 180-77706; Assy: LAN2; CAD_APPROVED: Yes; HEIGHT: 0.9mm; MFG_NAME01: Murata; MFG_PN01: LQM2MPN4R7NG0L; PART_TYPE: INDUCTOR\POWER; ROHS: Yes; ROOM: RGMII_PHY; SIGNAL_MODEL: DEFAULT_INDUCTOR_4700nH_2_1; SolidRun P/N: IN00030; Tolerance: 20%; Datasheet: http://search.murata.co.jp/Ceramy/image/img/PDF/ENG/L0075S0104LQM2MP_G0.pdf
L17 L19 L20 = Ferrite_Bead: Filter Bead 90ohms 25%; Assy: AUDIO; MFG_NAME01: VIKING; MFG_PN01: CB05YTYH900; Manufacturer: VIKING; Manufacturer P/N: CB05YTYH900; PRIORITY_PN: IN00001; SolidRun P/N: IN00001; Tolerance: 25%; Updated: 2015-07-16 09:53:12; Datasheet: <null>
R4 R285 R286 = Resistor: RES 0402 1/16W 4.7K? 5%; Manufacturer: Yageo; Manufacturer P/N: RC0402JR-074K7L; Part Number: R4720402-1%; Power: <null>; SolidRun P/N: RE20002; Tolerance: 5%; Datasheet: <null>
R6 = Resistor: RES 0402 1/16W 4.7K? 5%; Assy: DNP; Manufacturer: Yageo; Manufacturer P/N: RC0402JR-074K7L; Part Number: R4720402-1%; Power: <null>; SolidRun P/N: RE20002; Tolerance: 5%; Datasheet: <null>
R11 = Resistor: RES 0402 1/16W 1K 5%; FPLIST: 0402_SQR21,0402_RND,0402; Manufacturer: Yageo; Manufacturer P/N: RC0402FR-071KL; Part Number: R4720402-1%; SolidRun P/N: RE20010; Updated: 2015-02-17 20:35:06; Datasheet: <null>
R127-R130 = Resistor_tolerance_0: RES 0402 1/16W 75 1%; Assy: LAN2; FPLIST: RC0402_25,RC0402_HD,RC0402_X2,0402_CC; MFG_NAME01: YAGEO; MFG_PN01: RC0402JR-070RL; Manufacturer: Yageo; Manufacturer P/N: RC0402FR-0775RL; SolidRun P/N: RE20401; Updated: 2015-02-17 20:35:06; Datasheet: <null>
R131-R134 = Resistor_tolerance_0: RES 0402 1/16W 75 1%; FPLIST: RC0402_25,RC0402_HD,RC0402_X2,0402_CC; MFG_NAME01: YAGEO; MFG_PN01: RC0402JR-070RL; Manufacturer: Yageo; Manufacturer P/N: RC0402FR-0775RL; SolidRun P/N: RE20401; Updated: 2015-02-17 20:35:06; Datasheet: <null>
R135 = Resistor: RES 0402 1/16W 150 Ohm 1%; Manufacturer: Yageo; Manufacturer P/N: RC0402FR-0710KL; Part Number: R1030402-1%; Power: <null>; SolidRun P/N: RE20014; Tolerance: 5%; Datasheet: <null>
R191 = Resistor: RES 0402 1/16W 2.49 KOhm 1%; Assy: LAN2; Manufacturer: Yageo; Power: <null>; SolidRun P/N: RE20436; Tolerance: 1%; Datasheet: <null>
R193 = Resistor: RES 0402 1/16W 4.7K? 5%; Assy: LAN2; Manufacturer: Yageo; Manufacturer P/N: RC0402JR-074K7L; Part Number: R4720402-1%; Power: <null>; SolidRun P/N: RE20002; Tolerance: 5%; Datasheet: <null>
R278 = Resistor: RES 0402 1/16W 20K 1%; Assy: AUDIO; FPLIST: 0402_SQR21,0402_RND,0402; SolidRun P/N: RE20439; Datasheet: <null>
R279 = Resistor: RES 0402 1/16W 80 1%; Assy: AUDIO; Manufacturer: Yageo; Power: <null>; SolidRun P/N: RE20432; Tolerance: 1%; Datasheet: <null>
R280 = Resistor: RES 0402 1/16W 5.1 KOhm 1%; Assy: AUDIO; Manufacturer: Yageo; Power: <null>; SolidRun P/N: RE20422; Tolerance: 1%; Datasheet: <null>
R281 = Resistor: RES 0402 1/16W 20 KOhm 1%; Assy: AUDIO; Manufacturer: Yageo; Power: <null>; SolidRun P/N: RE20439; Tolerance: 1%; Datasheet: <null>
R282 = Resistor: RES 0402 1/16W 1K 5%; Assy: AUDIO; FPLIST: 0402_SQR21,0402_RND,0402; Manufacturer: Yageo; Manufacturer P/N: RC0402FR-071KL; Part Number: R4720402-1%; SolidRun P/N: RE20010; Updated: 2015-02-17 20:35:06; Datasheet: <null>
R283 = Resistor: CHIP RES 2.2K 1/16W 0402; Assy: AUDIO; MFG_NAME01: YAGEO; MFG_PN01: RC0402JR-072K2L; SolidRun P/N: RE20204; Tolerance: 5%
R284 = Resistor: RES 0402 1/16W 20 KOhm 1%; Assy: DNP; Manufacturer: Yageo; Power: <null>; SolidRun P/N: RE20439; Tolerance: 1%; Datasheet: <null>
RN7 = RESISTOR_DIP_4: Resistor Network 4.7K Ohm 5% 4 x 0402 SMT; MFG_NAME01: YAGEO; MFG_PN01: YC124-JR-074K7L; SolidRun P/N: RN00007; Tolerance: 5%; Datasheet: http://www.yageo.ru/pdf/YC124.pdf
SW2 = SW_PUSHBUTTON-SPST-2_SM_0: Area: 5x2.8; Manufacturer: ALPS; Price: 0.2; SolidRun P/N: SW00001; Source: Mouser; Source P/N: 688-SKSCLDE010; Datasheet: http://www3.alps.com/WebObjects/catalog.woa/E/PDF/Switch/Tact/SKSC/SKSC.PDF
T2 = ATPL-456R_0: 1000 BASE –T DUAL PORT PoE PLUS MAGNETICS MODULE SMT; SolidRun P/N: IC01002
TP1-TP14 TP18-TP21 TP24 TP25 TP27-TP29 = TestPoint: Assy: DNP; Manufacturer: PCB; Manufacturer P/N: NA; Power: <null>; SolidRun P/N: TP00001; Tolerance: NA; Datasheet: <null>
U23 = RTL8111G(S): Assy: LAN2; SolidRun P/N: IC01013
U34 = 74AVCH2T45GN: Dual-bit, dual-supply voltage level translator/transceiver; 3-state; SolidRun P/N: IC01021
U41 = TCT_switch_with_LED: SolidRun P/N: CO00558
U42 U43 = 74AVCH2T45GN: Dual-bit, dual-supply voltage level translator/transceiver; 3-state; Assy: UART; SolidRun P/N: IC01021
U46 = ALC662: Assy: AUDIO; SolidRun P/N: IC01064
U47 = OJ-001A-xxT0_0: Assy: AUDIO; SolidRun P/N: CO00575
Y4 = CXA-025000: 25MHz 2mm x 1.6mm xyz ppm; Assy: LAN2; Manufacturer: YOKETAN; Manufacturer P/N: S3225A025000-F10CCCA; Part Number: CXA-025000-3X4X23; SolidRun P/N: OC00014; Updated: 2015-02-17 20:35:06; Datasheet: <null>

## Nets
GND: BT1.MINUS(NEG) C1.2 C2.2 C3.1 C5.1 C7.2 C14.2 C17.2 C19.1 C20.1 C21.1 C31.1 C36.2 C37.2 C54.2 C55.2 C66.2 C67.1 C69.1 C93.1 C94.1 C123.1 C225.2 C226.2 C229.2 C231.2 C232.2 C235.2 C236.2 C237.2 C238.2 C239.1 C240.1 C241.1 C243.1 C244.2 C245.2 C248.2 C249.2 C264.1 C266.1 C267.1 C440.2 C441.1 C442.1 CON7.4(GND) CON7.7(GND_DRAIN) DM2.2 J1.37 J1.43 J1.44 J1.49 J1.50 J1.55 J1.56 J1.61 J1.62 J1.67 J1.68 J1.73 J1.74 J1.79 J1.80 J2.13 J2.19 J2.20 J2.25 J2.26 J2.31 J2.32 J2.37 J2.38 J2.43 J2.44 J2.49 J2.50 J2.55 J2.56 J2.61 J2.62 J2.67 J2.68 J2.73 J2.74 J2.79 J2.80 J3.22 J3.28 J3.34 J3.40 J3.46 J3.49 J3.80 J5.2 J8.2 J11.2(TMDS_Data2S) J11.5(TMDS_Data1S) J11.8(TMDS_Data0S) J11.11(TMDS_CLK1S) J11.17(DDC/CEC_GND) J25.1 J38.4 J39.1 J42.3 L3.2 R3.1 R20.2 R21.2 R28.2 R38.1 R45.2 R135.1 R191.1 R286.1 SW2.3 SW2.4 U4.3 U4.21 U4.27 U4.33 U4.39 U4.45 U4.51 U4.57 U4.69 U4.71 U4.73 U4.75 U5.4(GND) U5.7(GND) U5.13(GND) U5.16(GND) U7.6(VSS1) U7.G1 U7.G2 U7.G3 U7.G4 U8.5(GND) U8.7(EPAD) U10.6(GND) U11.2(GND) U11.5(GND) U11.8(GND) U11.11(GND) U11.14(CONFIG2_GND) U11.16(GND) U11.19(DP_PWR_RETURN) U12.6(GND) U23.33(EPAD) U25.1(GND) U25.4(GND) U25.7(GND) U33.1 U33.7 U33.18 U33.33 U33.39 U33.45 U33.51 U33.57 U33.63 U33.69 U33.75 U34.4(GND) U34.5(DIR) U38.2(EQ1) U38.8(EQ0) U38.17(OE_N) U38.24(HIZ_EN) U38.33(EPAD) U39.1(GND) U40.1(GND) U41.1 U41.2 U42.4(GND) U42.5(DIR) U43.4(GND) U45.4(GND) U45.5(DIR) U46.4(DVSS) U46.7(DVSS) U47.A(GND) Y4.2(GND[0]) Y4.4(GND[1])
GNDC: C1.1 C2.1 C87.1 C153.2 C230.1 C270.2 CON7.S1 CON7.S2 CON10.S1 CON10.S2 J11.S1 J11.S2 J11.S3 J11.S4 J30.1 J31.1 J32.1 J33.1 J38.3 R3.2 SW2.5(S1) U5.SH1 U5.SH2 U5.SH3 U5.SH4 U11.SH1 U11.SH2 U11.SH3 U11.SH4 U47.6(Shell)
V1P8A: C123.2 J1.1 J1.3 J1.5 J1.7 J1.9 J42.1 R4.1 R7.2 R275.1 U34.8(VCC(B)) U42.8(VCC(B)) U43.5(DIR) U43.8(VCC(B))
V1P8S: C239.2 C248.1 J1.11 J1.13 J1.15 U10.2(NO1) U39.2(VREF1) U40.2(VREF1) U45.8(VCC(B)) U46.9(DVDD_IO)
V3P3A: C36.1 C37.1 C240.2 J3.9 J3.10 J3.11 J3.12 J3.13 J3.14 J3.15 J3.17 J3.19 RN7.1 RN7.2 U33.2 U33.4 U33.72 U33.74 U34.1(VCC(A)) U42.1(VCC(A)) U43.1(VCC(A))
V3P3S: C14.1 C54.1 C55.1 C67.2 C225.1 C226.1 C241.2 C249.1 C440.1 D1.2(A) J3.21 J3.23 J3.25 J3.27 J3.29 J3.31 Q1.S R19.1 R46.2 R47.2 R193.1 R287.1 RN5.3 RN5.4 RN6.3 RN6.4 RN7.3 RN7.4 U4.2 U4.4 U4.70 U4.72 U4.74 U10.1(VCC) U10.5(NC1) U23.11(AVDD33) U23.23(VDDREG) U23.32(AVDD33) U38.1(VDD) U38.3(DDET) U38.18(VDD) U38.22(DDC_EN) U45.1(VCC(A)) U46.1(DVDD)
V5A_EN: DM1.2 J1.17
V5S: C20.2 C93.2 C94.2 C264.2 J1.2 J1.4 J1.6 J1.8 J1.10 J1.12 J1.14 J1.16 J11.18(5V) J43.1 L17.1 R31.2 RN5.1 RN5.2 U8.4(EN) U8.6(IN) U12.1(VCC) U41.6 U47.B(VCC)
V5S_USB: C17.1 C19.2 C21.2 C441.2 C442.2 CON7.1(VBUS) R31.1 U5.1(VBUS1) U5.10(VBUS2) U8.1(OUT)
VIN_3P3_BAT: J3.20 R11.1
AUD_LINK_BCLK: J3.51 R279.2
AUD_LINK_RST_N: J3.45 U46.11(RESET_N)
AUD_LINK_SDIO_SOC: J3.53 U46.8(SDATA_IN)
AUD_LINK_SDO: J3.43 U46.5(SDATA_OUT)
AUD_LINK_SYNC: J3.47 U46.10(SYNC)
AUDIO_AGND: C261.2 DM2.1 J40.1 R278.1 U46.26(AVSS) U46.42(AVSS) U47.1(Earth_Spring) U47.4(Transfer_Terminal)
AUXN: U11.17(AUX_CH_M) U12.9(COM2)
AUXP: U11.15(AUX_CH_P) U12.3(COM1)
BT_LED2: U33.16
CONFIG1: R28.1 U11.13(CONFIG1_GND) U12.4(SEL1) U12.8(SEL2)
DDI0_1_SCL_1P8: J1.32 U40.3(SCL1)
DDI0_1_SDA_1P8: J1.34 U40.4(SDA1)
DDI1_AUXN: J1.42
DDI1_AUXP: J1.40
DDI1_HPD: J1.38 U38.5(HPD_SOURCE)
DDI1_TXN_0: C45.2 J1.48
DDI1_TXN_1: C43.2 J1.54
DDI1_TXN_2: C41.2 J1.60
DDI1_TXN_CLK: C47.2 J1.66
DDI1_TXP_0: C46.2 J1.46
DDI1_TXP_1: C44.2 J1.52
DDI1_TXP_2: C42.2 J1.58
DDI1_TXP_CLK: C48.2 J1.64
DDI2_AUXN: C64.2 J1.65
DDI2_AUXP: C65.2 J1.63
DDI2_HPD: J1.35 U11.18(HPD)
DDI2_SCL_1P8: J1.31 U39.3(SCL1)
DDI2_SCL_3P3S: RN6.6 U12.2(NO1) U39.6(SCL2)
DDI2_SDA_1P8: J1.33 U39.4(SDA1)
DDI2_SDA_3P3S: RN6.5 U12.10(NO2) U39.5(SDA2)
DDI2_TXN_0: C60.2 J1.41
DDI2_TXN_1: C58.2 J1.47
DDI2_TXN_2: C56.2 J1.53
DDI2_TXN_CLK: C63.2 J1.59
DDI2_TXP_0: C61.2 J1.39
DDI2_TXP_1: C59.2 J1.45
DDI2_TXP_2: C57.2 J1.51
DDI2_TXP_CLK: C62.2 J1.57
DEVSLP1: U4.38 U45.2(1A)
GPIO_SUS1: J1.29 TP11.1(TP)
GPIO_SUS2: J1.36 TP14.1(TP)
GPIO_SUS5: J1.21 R6.1
GPIO_SUS7: J1.27 R285.2 R286.2 TP10.1(TP)
HDA_FRONT_L: C262.1 U46.35(FRONT_L)
HDA_FRONT_R: C263.1 U46.36(FRONT_R)
HDA_SPDIFO: U46.48(SPDIFO) U47.C(Vin)
HDMI_CEC: J1.23 J11.13(CEC)
HDMI_CLK_DN: C47.1 U38.25(IN_D1-)
HDMI_CLK_DP: C48.1 U38.26(IN_D1+)
HDMI_D0_DN: C41.1 U38.27(IN_D2-)
HDMI_D0_DP: C42.1 U38.28(IN_D2+)
HDMI_D1_DN: C43.1 U38.29(IN_D3-)
HDMI_D1_DP: C44.1 U38.30(IN_D3+)
HDMI_D2_DN: C45.1 U38.31(IN_D4-)
HDMI_D2_DP: C46.1 U38.32(IN_D4+)
HDMI_HPD: J11.19(HPD) U38.21(HPD_SINK)
HDMI_SCL: J11.15(SCL) RN5.8 U38.19(SCP_SINK)
HDMI_SDA: J11.16(SDA) RN5.7 U38.20(SDA_SINK)
HDMI_TX_DDC_SCL: RN5.5 U38.7(SCL_SOURCE) U40.6(SCL2)
HDMI_TX_DDC_SDA: RN5.6 U38.6(SDA_SOURCE) U40.5(SDA2)
I2C4_SCL: J3.16
I2C4_SDA: J3.18
IR: J3.79
JDREF: R278.2 U46.40(JDREF)
LAN_P0_LED0: CON10.B9 J3.33
LAN_P0_LED1: J3.35
LAN_P0_LED2: CON10.B11 J3.37
LAN_P1_ISOLATE_1P8: J2.14
LAN_P1_ISOLATE_N: R193.2 U23.20(ISOLATEB)
LAN_P1_LED0: CON10.A9 U23.27(LED0)
LAN_P1_LED1: U23.26(LED1/GPO)
LAN_P1_LED2: CON10.A11 U23.25(LED2)
MCU_PA0: J3.75 R285.1
MCU_PA1: J3.77 TP18.1(TP)
MCU_PA2: J3.67 TP20.1(TP)
MCU_PA3: J3.63 TP19.1(TP)
MCU_PA4: J3.61 TP21.1(TP)
MIC_IN: J40.3 R282.2 R283.1
NGFF_DISABLE1_N: U33.56
NGFF_DISABLE2_N: U33.54
OUT_LEFT: C267.2 L19.2 U47.2(Tip_Spring)
OUT_RIGHT: C266.2 L20.2 U47.3(Ring_Spring)
P0_MDIN0: J3.26 T2.15
P0_MDIN1: J3.32 T2.18
P0_MDIN2: J3.38 T2.21
P0_MDIN3: J3.44 T2.24
P0_MDIP0: J3.24 T2.14
P0_MDIP1: J3.30 T2.17
P0_MDIP2: J3.36 T2.20
P0_MDIP3: J3.42 T2.23
P1_MDIN0: T2.3 U23.2(MDIN0)
P1_MDIN1: T2.6 U23.5(MDIN1)
P1_MDIN2: T2.9 U23.7(MDIN2)
P1_MDIN3: T2.12 U23.10(MDIN3)
P1_MDIP0: T2.2 U23.1(MDIP0)
P1_MDIP1: T2.5 U23.4(MDIP1)
P1_MDIP2: T2.8 U23.6(MDIP2)
P1_MDIP3: T2.11 U23.9(MDIP3)
PANEL1_BKLTCTL: J1.20
PANEL1_BKLTEN: J1.18
PANEL1_VDDEN: J1.22
PCIE_CLK_N_0: J2.29
PCIE_CLK_N_1: J2.23 U33.49
PCIE_CLK_N_3: J2.17 U23.16(REFCLK_N)
PCIE_CLK_P_0: J2.27
PCIE_CLK_P_1: J2.21 U33.47
PCIE_CLK_P_3: J2.15 U23.15(REFCLK_P)
PCIE_CLKREQ0B: J3.55
PCIE_CLKREQ1B: J3.57 U33.53
PCIE_CLKREQ3B: J3.59 U23.12(CLKREQB)
PCIE_RXN0: J2.22
PCIE_RXN1: J2.28 U33.43
PCIE_RXN3: C224.1 J2.34
PCIE_RXP0: J2.24
PCIE_RXP1: J2.30 U33.41
PCIE_RXP3: C223.1 J2.36
PCIE_TXN0: J2.33
PCIE_TXN1: C38.1 J2.39
PCIE_TXN3: C234.2 J2.45
PCIE_TXP0: J2.35
PCIE_TXP1: C35.1 J2.41
PCIE_TXP3: C233.2 J2.47
PMU_AC_PRESENT: J2.1 R4.2
PMU_BATLOW_B: J2.9 TP5.1(TP)
PMU_PLTRST_3P3_B: U23.19(PERSTB) U33.52 U34.3(2A)
PMU_PLTRST_B: J2.8 TP9.1(TP) U34.6(2B)
PMU_PWRBTN_N: J2.18 U41.3 U41.4
PMU_RESETBUTTON_B: J2.7 J8.8 SW2.1 SW2.2
PMU_SLP_S0IX_B: J1.25 TP12.1(TP)
PMU_SLP_S3_N: J2.3 TP3.1(TP)
PMU_SLP_S4_N: J1.19 TP13.1(TP)
PMU_SUSCLK_1P8: J2.11 U34.7(1B)
PMU_SUSCLK_3P3: U33.50 U34.2(1A)
PMU_WAKE_N: J2.16 R275.2 TP8.1(TP) U33.55
Power Data+: J38.5 R132.1 T2.33
Power Data-: J38.7 R131.1 T2.36
Power Spare+: J38.6 R133.1 T2.30
Power Spare-: J38.8 R134.1 T2.27
PROCHOT_B: J2.5 TP4.1(TP)
REGOUT_LDO_P1: C235.1 C236.1 C237.1 C238.1 L15.2 R192.1 U23.3(AVDD10) U23.8(AVDD10) U23.22(DVDD10) U23.30(AVDD10)
REGOUT_P1: C229.1 L15.1 R192.2 U23.24(REGOUT)
RSMRST: J3.52 TP1.1(TP)
RXD1: J25.3 U43.2(1A)
RXD2: J39.3 U43.3(2A)
SATA_DEVSLP0_1P8: J3.48
SATA_DEVSLP1_1P8: J3.50 U45.7(1B)
SATA_LED_3P3_N: LED18.C(CATHODE) U45.3(2A)
SATA_LED_N: J3.39 U45.6(2B)
SATA_RXN0: C51.1 J1.72
SATA_RXN1: C10.1 J1.69
SATA_RXP0: C52.1 J1.70
SATA_RXP1: C9.1 J1.71
SATA_TXN0: C50.1 J1.76
SATA_TXN1: C11.1 J1.77
SATA_TXP0: C49.1 J1.78
SATA_TXP1: C12.1 J1.75
SDMMC3_1P8_EN: J3.62 R20.1 U10.4(SEL1)
SDMMC3_CD_B: J3.66 U7.9(Cd)
SDMMC3_CLK: J3.78 U7.5(CLK)
SDMMC3_CMD: J3.76 U7.3(CMD)
SDMMC3_D0: J3.74 U7.7(D0)
SDMMC3_D1: J3.72 U7.8(D1)
SDMMC3_D2: J3.70 U7.1(D2)
SDMMC3_D3: J3.68 U7.2(CD/D3)
SDMMC3_PWR_EN: J3.64 Q1.G R21.1
SENSEA: R280.1 R281.1 R284.1 U46.13(SENSE_A)
SENSEB: U46.34(SENSE_B)
SPI_CLK: J1.24 J8.4
SPI_CS: J1.26 J8.3
SPI_D0: J1.28 J8.6
SPI_D1: J1.30 J8.5
SPKR: J3.41 TP2.1(TP)
SUS_STAT_N: J2.10 TP7.1(TP)
SWITCH: R280.2 R281.2 R284.2 U47.5(Make_Terminal)
TMDS0+: J11.7(TMDS_Data0+) U38.13(OUT_D2+)
TMDS0-: J11.9(TMDS_Data0-) U38.14(OUT_D2-)
TMDS1+: J11.4(TMDS_Data1+) U38.11(OUT_D3+)
TMDS1-: J11.6(TMDS_Data1-) U38.12(OUT_D3-)
TMDS2+: J11.1(TMDS_Data2+) U38.9(OUT_D4+)
TMDS2-: J11.3(TMDS_Data2-) U38.10(OUT_D4-)
TMDSCLK+: J11.10(TMDS_CLK1+) U38.15(OUT_D1+)
TMDSCLK-: J11.12(TMDS_CLK1-) U38.16(OUT_D1-)
TXD1: J25.2 U42.2(1A)
TXD2: J39.2 U42.3(2A)
UART1_CTS_B: J3.58 TP24.1(TP)
UART1_RTS_B: J3.60 TP25.1(TP)
UART1_RXD: J3.56 U43.7(1B)
UART1_TXD: J3.54 U42.7(1B)
UART2_CTS_B: J2.4
UART2_RTS_B: J2.6
UART2_RXD: J3.71 U43.6(2B)
UART2_TXD: J3.73 U42.6(2B)
USB3_RXN0: J2.40 L7.3
USB3_RXN1: J2.46 L9.2
USB3_RXN2: J2.52 L1.2
USB3_RXN3: J2.66
USB3_RXP0: J2.42 L7.2
USB3_RXP1: J2.48 L9.3
USB3_RXP2: J2.54 L1.3
USB3_RXP3: J2.64
USB3_TXN0: C33.2 J2.58
USB3_TXN1: C39.2 J2.51
USB3_TXN2: C15.2 J2.59
USB3_TXN3: J2.63
USB3_TXP0: C34.2 J2.60
USB3_TXP1: C40.2 J2.53
USB3_TXP2: C16.2 J2.57
USB3_TXP3: J2.65
USB_DN0: J2.77 T6.2(IN2)
USB_DN1: J2.70 T3.2(IN2)
USB_DN2: J2.71 T1.3(OUT2)
USB_DN3: J2.78 U33.5
USB_DP0: J2.75 T6.3(OUT2)
USB_DP1: J2.72 T3.3(OUT2)
USB_DP2: J2.69 T1.2(IN2)
USB_DP3: J2.76 U33.3
USB_OC0_B: J3.69 U8.3(FLAG#)
USB_OC1_B: J3.65 TP27.1(TP)
USB_OTG_ID: J2.2 J42.2 TP6.1(TP)
V_DCJACK_CM: C8.2 C270.1 CON1.1(V) J38.1 L2.1
V_SD: C7.1 Q1.D U7.4(VDD)
VMAIN0: R129.1 T2.42
VMAIN1: R128.1 T2.45
VPORT_NEG0: R130.1 T2.39
VPORT_NEG1: R127.1 T2.48
VSDIO: C31.2 J2.12 R19.2 U10.3(COM1)
VSYS: C3.2 C5.2 DM1.1 J3.1 J3.2 J3.3 J3.4 J3.5 J3.6 J3.7 J3.8 J38.2 L2.2
WIFI_LED1: U33.6
N16200: C9.2 U4.41
N16204: C10.2 U4.43
N16224: C11.2 U4.47
N16236: C12.2 U4.49
N16405672: C15.1 L4.2
N16405676: C16.1 L4.3
N16778284: J5.1 R6.2
N16778893: J8.1 R7.1
N16786078: C49.2 U25.2(TXp)
N16786084: C50.2 U25.3(TXn)
N16786090: C51.2 U25.5(RXn)
N16786096: C52.2 U25.6(RXp)
N16796812: C35.2 U33.35
N16796843: C38.2 U33.37
N16811644: T1.4(OUT1) U5.2(D1-)
N16811647: T1.1(IN1) U5.3(D1+)
N16812099: L1.4 U5.6(SSRX1+)
N16813187: L1.1 U5.5(SSRX1-)
N16813227: L4.1 U5.8(SSTX1-)
N16813230: L4.4 U5.9(SSTX1+)
N16813384: C33.1 L8.3
N16813386: C34.1 L8.2
N16813430: T6.1(IN1) U5.11(D2-)
N16813432: T6.4(OUT1) U5.12(D2+)
N16813446: L7.1 U5.15(SSRX2+)
N16813454: L7.4 U5.14(SSRX2-)
N16813460: L8.4 U5.17(SSTX2-)
N16813462: L8.1 U5.18(SSTX2+)
N16847343: R38.2 U38.4(REXT)
N16853647: R45.1 U8.2(ILIM)
N16864723: C61.1 U11.1(ML_LANE0_P)
N16864726: C60.1 U11.3(ML_LANE0_M)
N16864756: C59.1 U11.4(ML_LANE1_P)
N16864759: C58.1 U11.6(ML_LANE1_M)
N16864762: C57.1 U11.7(ML_LANE2_P)
N16864765: C56.1 U11.9(ML_LANE2_M)
N16864768: C62.1 U11.10(ML_LANE3_P)
N16864771: C63.1 U11.12(ML_LANE3_M)
N16867107: C66.1 D1.1(K) U11.20(DP_PWR)
N16869009: CON7.5(StdA_SSRX-) L9.1
N16869014: CON7.9(StdA_SSTX+) L10.1
N16869018: C39.1 L10.3
N16869020: C40.1 L10.2
N16869028: CON7.6(StdA_SSRX+) L9.4
N16869031: CON7.8(StdA_SSTX-) L10.4
N16869067: CON7.3(D+) T3.4(OUT1)
N16869069: CON7.2(D-) T3.1(IN1)
N16875394: C65.1 U12.5(NC1)
N16875397: C64.1 U12.7(NC2)
N16882247: R46.1 U39.7(VREF2) U39.8(EN)
N16885660: R47.1 U40.7(VREF2) U40.8(EN)
N16891748: C69.2 T2.13 T2.16 T2.19 T2.22
N16891979: C243.2 T2.1 T2.4 T2.7 T2.10
N16892041: CON10.A3 T2.44
N16892043: CON10.A6 T2.43
N16892047: CON10.A4 T2.41
N16892049: CON10.A7 T2.38
N16892051: CON10.A8 T2.37
N16892055: CON10.A5 T2.40
N16892061: CON10.A2 T2.46
N16892063: CON10.A1 T2.47
N16892081: CON10.B3 T2.32
N16892083: CON10.B6 T2.31
N16892087: CON10.B4 T2.29
N16892089: CON10.B7 T2.26
N16892091: CON10.B8 T2.25
N16892095: CON10.B5 T2.28
N16892101: CON10.B2 T2.34
N16892103: CON10.B1 T2.35
N16892121: C87.2 C215.2 C216.2 C217.2 C218.2
N16892189: C215.1 R127.2
N16892191: C216.1 R128.2
N16892206: C217.1 R129.2
N16892220: C218.1 R130.2
N16892244: C219.2 C220.2 C221.2 C222.2 C230.2
N16892302: C219.1 R131.2
N16892304: C220.1 R132.2
N16892320: C221.1 R133.2
N16892333: C222.1 R134.2
N16900318: CON10.B10 RN7.8
N16900351: CON10.B12 RN7.7
N16900369: CON10.A10 RN7.6
N16900381: CON10.A12 RN7.5
N16910042: C231.1 U23.29(CKXTAL2) Y4.3(X2)
N16910044: R191.2 U23.31(RSET)
N16910175: C233.1 U23.13(HSIP)
N16910177: C234.1 U23.14(HSIN)
N16910179: C223.2 U23.17(HSOP)
N16910190: C224.2 U23.18(HSON)
N16910230: C232.1 U23.28(CKXTAL1) Y4.1(X1)
N16951757: LED18.A(ANODE) R287.2
N16966126: C269.2 U46.22(MIC1_R)
N16966136: TP29.1(TP) U46.24(LINE1_R)
N16966138: TP28.1(TP) U46.23(LINE1_L)
N16966256: C244.1 C245.1 L17.2 U46.25(AVDD) U46.38(AVDD)
N16979567: R279.1 U46.6(BITCLK)
N16982347: R283.2 U46.32(MIC1_VREFO_R)
N16986074: C261.1 U46.27(VREF)
N16994048: C262.2 L19.1
N16995812: C263.2 L20.1
N16996986: C268.1 C269.1 R282.1
N16997878: C268.2 U46.21(MIC1_L)
N17047086: C8.1 C153.1 CON1.2(GND[0]) CON1.3(GND[1]) L3.1
N17055718: R135.2 U41.5
N17056680: BT1.PLUS(POS) R11.2

Not connected (* = marked no-connect by the designer): J7 1; J8 7; J11 14(Reserve)*; J12 1; J18 1; J19 1; J27 1; J40 2; J41 1 2; J43 2; RN6 1 2 7 8; U4 1 5 6 7 8 9 10 11 12 13 14 15 16 17 18 19 20 22 23 24 25 26 28 29 30 31 32 34 35 36 37 40 42 44 46 48 50 52 53 54 55 56 58 59 60 61 62 63 64 65 66 67 68; U10 7(NC2) 8(SEL2) 9(COM2) 10(NO2); U23 21(LANWAKEB); U33 8 9 10 11 12 13 14 15 17 19 20 21 22 23 24 25 26 27 28 29 30 31 32 34 36 38 40 42 44 46 48 58 59 60 61 62 64 65 66 67 68 70 71 73; U38 23(n.c.)*; U46 2(GPIO0)* 3(GPIO1)* 12(PCBEEP) 14(LINE2_L)* 15(LINE2_R)* 16(MIC2_L)* 17(MIC2_R)* 18(CD_L)* 19(CD_GND)* 20(CD_R)* 28(MIC1_VREFO_L) 29(NC)* 30(MIC2_VREFO)* 31(LINE2_VREFO)* 33(NC)* 37(NC)* 39(SURR_L)* 41(SURR_R)* 43(CENTER)* 44(LFE)* 45(NC)* 46(NC)* 47(EAPD)*

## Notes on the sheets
sheet 1
- SOM IBxxxx connectivity
- OTG selection header.
  Since host connector is used, OTG ID is
  floating and can be choosen here while
  using a USB host-to-host cable to have
  the USB device function.
- UART level shifters and headers
- Misc test points
- A=B
- platform reset - 1.8v
- B=A
- Mechanical spacers on the print side of the board
- MCU Wakeup circuit.
  Level shifts through resistors from 3.3v to 1.8v.
  Notice that this function is not used when programming
  the on SOM MCU to have HDMI CEC and the wake-up
  function is implemented as wake-on-usb (i.e. MCU
  wakes up the main processor via USB).
- MECH_X_Y is a mechanical hole that the hole size is
  X mm and padstack is Y mm.
  J30, J31, J32 and J33 are M2.5
  J18, J19 and J27 are M1.8
- MECH_X_Y is a mechanical hole that the hole size
  is X mm and padstack is Y mm.
  J18, J19 and J27 are M1.8
- HDMI on DDI2.
  DP on DDI1
- Mandatory components
- GPIO_SUS5 must be connected to GND when replacing BIOS flash descriptor
  PMU_AC_PRESENT pulled up to indicate wall AC-DC powered
  V5A_EN is enable for the SOM - DM1 is a dummy resistor that is implemented as an etch
- PORT-1  MDI I/F
- Enable the whole uSOM
- Note the addition of C440.
  Version 1.1 and 1.2 did not have this capacitor, so there
  wasn't enough capacitance on this rail which caused lots of CRC errors.
- DM is a PCB etch that is equivalent to zero ohm.
  It's implemented as an etch rather than phyiscal zero
  ohm resistor to spare an assembly.
- Circuit is being ran from AC
  and not battery.
- DC jack with lock
- Bulk capacitors to be placed on output of MicroSOM
- Implementation note -
  C69 and C243 are shared capacitor on magnetics center tap.
  This implementation is ok when using voltage mode phys.
  For current mode phys each center tap should have it's
  own capacitor.
- LAN0 is always on (WoL support)
  LAN1 is supplied from V3P3S
- PORT-0  MDI I/F
- LED2 - activity and link
- R192 can be used when having RTL8111G (internal LDO
  version); i.e. not the RTL8111GS version.
- PoE Header
- Power on button, reset and battery
- JD_FRONT
- Notice VF is 3.0v to 3.6v
  Part used is TLLA-72BB-R1KH1-V-B
- JD_MIC1
- SolidPC rev 1.3
- R284 is place holder
- Components without ASSY=xx are always assembled
  Components with ASSY=DNP are do-not-place (i.e. not placed)
  Components with ASSY=<feature> are marking for feature wise assembly options
  Components with thick boundary like this -->
  are must for proper SOM functionality
- Notes -
  1. J38 and J43 can be used to connecto to an external PoE PCB module.
  2. J43 can be usd as indication for PoE adapter
      board if the SOM is in standby mode or not.
      This is useful in case the SOM is in standby where the
      PoE source must see minimum load in order to keep
      the circuit powered.
      V5S can be used to enable a constant load when V5S
      is low (i.e. SOM in standby).
- Make sure in layout there is a close by capacitor to V1P8A and V3P3A
- BIOS Flashing 8 pin 100mil header
- A=B
- Notice that R7 must never be assembled since it shorts
  to V1P8A.
  It's here only for debug purposes.
  Typically it is used to power the SPI flash on the uSOM when
  the rest of the uSOM is powered down; but in this case the
  uSOM must be powered on and the reset signal will hold it from
  using the SPI flash.
  Notice that the programmer must drive 1.8v signals; otherwise
  the main processor might get damaged.
- DM2 is a PCB etch that shorts GND and AUDIO_AGND
sheet 2
- Right angle power on/off switch
- 3x USB 3.0 out
- DP++ connector
- Notice D1 where in recent versions V3P3S was directly connected
  to the DP connector (bug fix)
- Notice the addition of more capacitance on the output C441 and C442.
  This comes to assist when using external mechanical devices.
  The issue that was observed is high swing on VBus when
  using external USB CD-ROM/DVD.
- External SATA connector
- Notes -
  1. Typically not soldered on the board.
  2. Previous revs had a bug on RXN0 and RXP0 were
      they where swapped
- M.2 2242 SSD connector
- HDMI level shifter
- pin 21 SSD_CONFIG0
- [TYPE-A]
- Notice that the power rails of the level shitfter and not
  decoupled since there are near by capacitors for
  other functions on the board.
- Notice EQ0 and EQ1 are set to 00; i.e. highest dbm
  the level shifter can have. Unclear if this is needed or not.
- A=B
- pin 69 - M.2_SSD_PEDET
- pin 75 - SSD_CONFIG3
- MicroSD with 3.3v/1.8 switchover for UHS-1
- Key-E
- M.2 2230 WiFi/BT connector
- 5V
- Add ESD protection on CEC
- J41 is a dummy two pin 100 mil header
  Might be used to hold Wifi antennas
- Replace with 1.8v I2C
- NGFF_DISABLE1_N - WiFi disable when low
  NGFF_DISABLE2_N - BT disable when low
- pin 69 - M.2_SSD_PEDET
- pin 75 - SSD_CONFIG3
